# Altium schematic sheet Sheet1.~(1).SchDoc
size A4
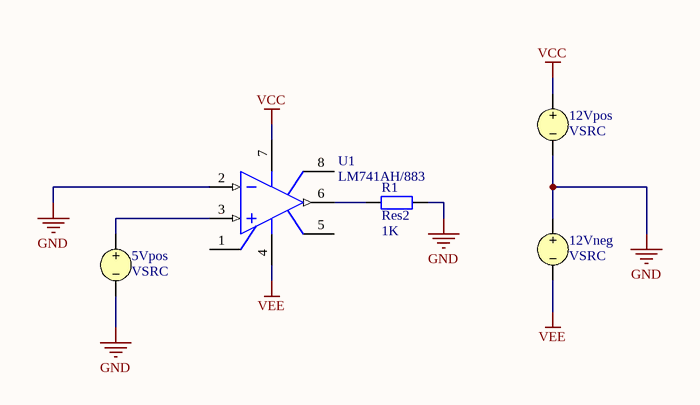
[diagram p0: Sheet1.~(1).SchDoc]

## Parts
5Vpos  VSRC
12Vneg  VSRC
12Vpos  VSRC
R1  Res2  value 1K  [AXIAL-0.4]
U1  LM741AH/883  [H08C]

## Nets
GND: 5Vpos.2 12Vneg.1 12Vpos.2 R1.2 U1.2(IN-)
VCC: 12Vpos.1 U1.7(V+)
VEE: 12Vneg.2 U1.4(V-)
Net5Vpos_1: 5Vpos.1 U1.3(IN+)
NetR1_1: R1.1 U1.6(OUT)

Not connected (* = marked no-connect by the designer): U1 1(OS_NULL) 5(OS_NULL) 8(NC)

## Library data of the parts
5Vpos = VSRC: Voltage Source; Note: PCB Footprint - Not required; Value: +5
12Vneg = VSRC: Voltage Source; Note: PCB Footprint - Not required; Value: -12
12Vpos = VSRC: Voltage Source; Note: PCB Footprint - Not required; Value: +12
R1 = Res2: Resistor
U1 = LM741AH/883: Operational Amplifier; ComponentAvailability: Obsolete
